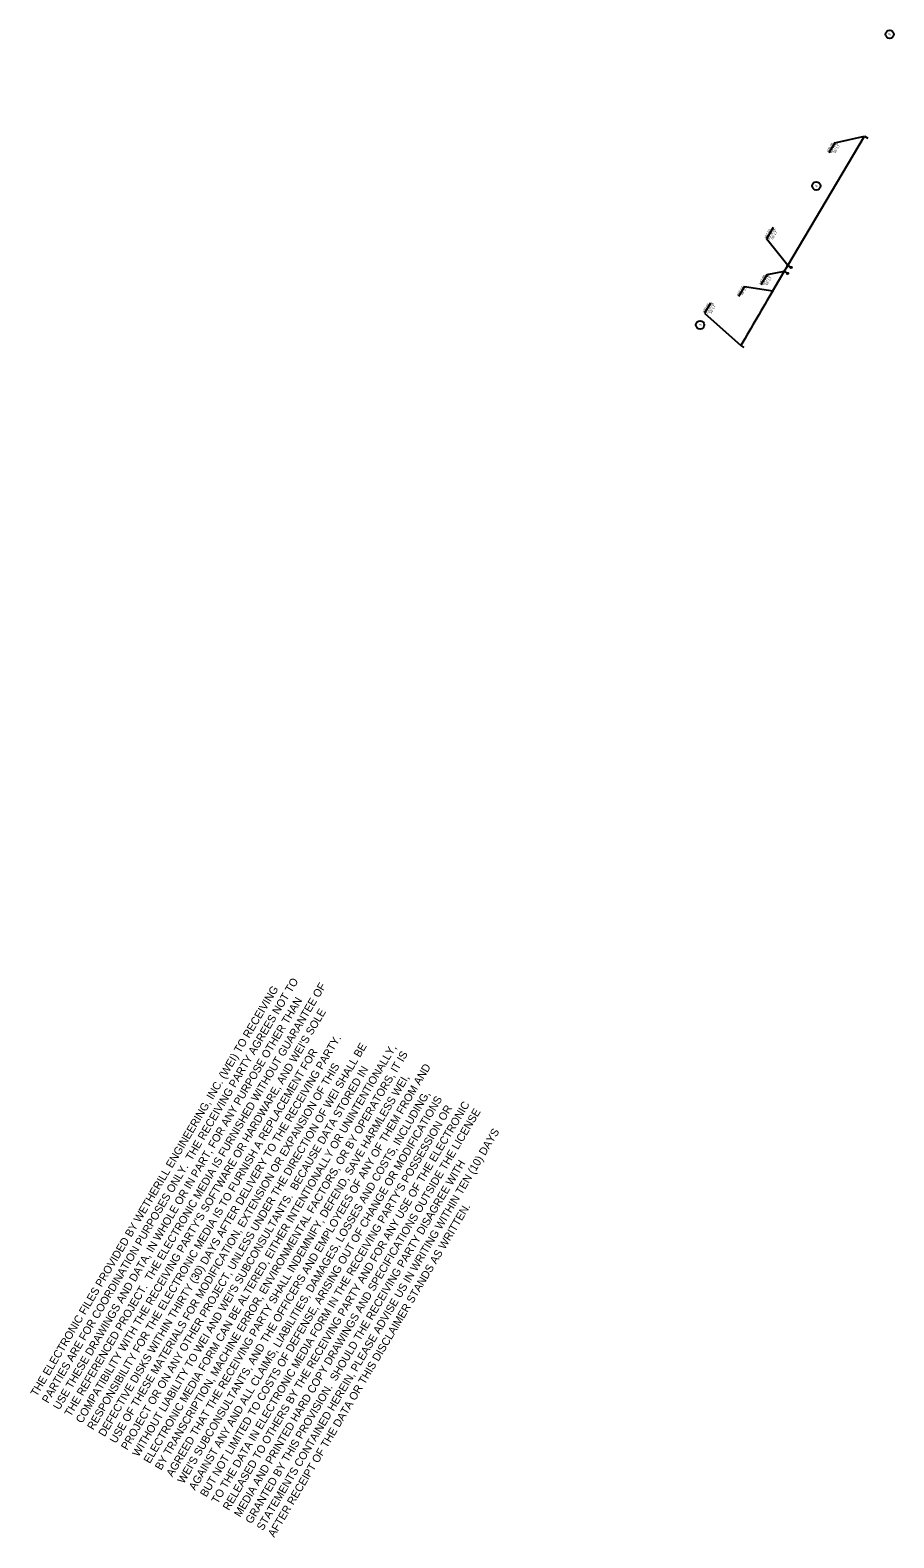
# Model space of a CAD drawing. Extents: x 2138768 to 2141259, y 406633 to 410979.
import ezdxf

# ---------------------------------------------------------------- set-up
doc = ezdxf.new("R2010")
doc.units = 0
for name, color, linetype in [('Default', 7, 'Continuous'), ('Prop Easement Construction', 7, 'Continuous'), ('Prop Easement Construction Station Offsets', 7, 'Continuous'), ('Prop Easement Permanent Drainage', 7, 'Continuous'), ('Prop Easement Permanent Drainage Station Offsets', 7, 'Continuous'), ('Prop Parcel Number CELL', 7, 'Continuous'), ('Prop ROW Marker CELL', 7, 'Continuous'), ('Prop ROW Permanent Easement CELL', 7, 'Continuous')]:
    doc.layers.add(name, color=color, linetype=linetype)

msp = doc.modelspace()

# ---------------------------------------------------------------- linework, layer by layer
at = {"layer": 'Prop Easement Construction'}
for p, q in [((2140952.9, 410300.7), (2141173.9, 410673)), ((2141173.9, 410673), (2141183.8, 410667.1)), ((2140909.6, 410227.8), (2140942.7, 410283.5)), ((2140817.4, 410069.5), (2140826.2, 410064.5))]:
    msp.add_line(p, q, dxfattribs=at)
msp.add_arc((2150502.2, 404534.3), 11155, 149.30926, 150.25022, dxfattribs=at)
at = {"layer": 'Prop Easement Construction Station Offsets'}
for p, q in [((2141088.6, 410654.4), (2141071.5, 410625.4)), ((2140828.3, 410240.4), (2140811.2, 410211.6)), ((2140730.4, 410191.8), (2140713.2, 410162.8))]:
    msp.add_line(p, q, dxfattribs=at)
for points in [[(2141088.6, 410654.4), (2141173.9, 410673)], [(2140828.3, 410240.4), (2140909.6, 410227.8)], [(2140713.2, 410162.8), (2140817.4, 410069.5)]]:
    msp.add_lwpolyline(points, dxfattribs=at)
at = {"layer": 'Prop Easement Permanent Drainage'}
for p, q in [((2140942.7, 410283.5), (2140952.9, 410300.7)), ((2140952.9, 410300.7), (2140962.8, 410294.8)), ((2140952.6, 410277.6), (2140942.7, 410283.5))]:
    msp.add_line(p, q, dxfattribs=at)
at = {"layer": 'Prop Easement Permanent Drainage Station Offsets'}
for p, q in [((2140910.5, 410409.8), (2140891.5, 410377.7)), ((2140952.9, 410300.7), (2140891.5, 410377.7)), ((2140892.4, 410273.6), (2140875.2, 410244.7)), ((2140942.7, 410283.5), (2140892.4, 410273.6))]:
    msp.add_line(p, q, dxfattribs=at)
at = {"layer": 'Prop Parcel Number CELL'}
for p, q in [((2141246.8, 410966.9), (2141246.8, 410966.9)), ((2141035.1, 410530), (2141035.1, 410530)), ((2140700, 410129.3), (2140700, 410129.3))]:
    msp.add_line(p, q, dxfattribs=at)
for centre in [(2141246.8, 410966.9), (2141035.1, 410530), (2140700, 410129.3)]:
    msp.add_circle(centre, 12, dxfattribs=at)
at = {"layer": 'Prop ROW Marker CELL'}
for p, q in [((2140952.9, 410300.7), (2140952.9, 410300.7)), ((2140962.8, 410294.8), (2140962.8, 410294.8)), ((2140942.7, 410283.5), (2140942.7, 410283.5)), ((2140952.6, 410277.6), (2140952.6, 410277.6))]:
    msp.add_line(p, q, dxfattribs=at)
at = {"layer": 'Prop ROW Permanent Easement CELL'}
for points in [[(2140951, 410301.8), (2140954, 410302.5), (2140954.7, 410299.6), (2140951.8, 410298.8)], [(2140952, 410301.2), (2140953.4, 410301.6), (2140953.8, 410300.1), (2140952.3, 410299.8)], [(2140961, 410295.9), (2140963.9, 410296.6), (2140964.7, 410293.7), (2140961.7, 410292.9)], [(2140961.9, 410295.3), (2140963.4, 410295.7), (2140963.8, 410294.2), (2140962.3, 410293.9)], [(2140940.8, 410284.6), (2140943.8, 410285.3), (2140944.5, 410282.4), (2140941.6, 410281.6)], [(2140941.7, 410284), (2140943.2, 410284.4), (2140943.6, 410282.9), (2140942.1, 410282.6)], [(2140950.8, 410278.7), (2140953.7, 410279.4), (2140954.5, 410276.5), (2140951.5, 410275.7)], [(2140951.7, 410278.1), (2140953.2, 410278.5), (2140953.6, 410277), (2140952.1, 410276.7)]]:
    msp.add_lwpolyline(points, close=True, dxfattribs=at)

# ---------------------------------------------------------------- texts
at = {"layer": 'Default'}
for s, p in [('THE ELECTRONIC FILES PROVIDED BY WETHERILL ENGINEERING, INC. (WEI) TO RECEIVING ', (2138787.2, 407038.8)), ('PARTIES ARE FOR COORDINATION PURPOSES ONLY.  THE RECEIVING PARTY AGREES NOT TO ', (2138819.8, 407019.4)), ('THE REFERENCED PROJECT.  THE ELECTRONIC MEDIA IS FURNISHED WITHOUT GUARANTEE OF ', (2138885, 406980.8)), ('USE THESE DRAWINGS AND DATA, IN WHOLE OR IN PART, FOR ANY PURPOSE OTHER THAN ', (2138852.4, 407000.1)), ("COMPATIBILITY WITH THE RECEIVING PARTY'S SOFTWARE OR HARDWARE, AND WEI'S SOLE ", (2138917.6, 406961.5)), ('DEFECTIVE DISKS WITHIN THIRTY (30) DAYS AFTER DELIVERY TO THE RECEIVING PARTY.  ', (2138982.8, 406922.8)), ('RESPONSIBILITY FOR THE ELECTRONIC MEDIA IS TO FURNISH A REPLACEMENT FOR ', (2138950.2, 406942.2)), ('PROJECT OR ON ANY OTHER PROJECT, UNLESS UNDER THE DIRECTION OF WEI SHALL BE ', (2139048, 406884.2)), ('ELECTRONIC MEDIA FORM CAN BE ALTERED, EITHER INTENTIONALLY OR UNINTENTIONALLY, ', (2139113.1, 406845.5)), ('BY TRANSCRIPTION, MACHINE ERROR, ENVIRONMENTAL FACTORS, OR BY OPERATORS, IT IS ', (2139145.7, 406826.2)), ('USE OF THESE MATERIALS FOR MODIFICATION, EXTENSION OR EXPANSION OF THIS ', (2139015.4, 406903.5)), ("WITHOUT LIABILITY TO WEI AND WEI'S SUBCONSULTANTS.  BECAUSE DATA STORED IN ", (2139080.6, 406864.9)), ("WEI'S SUBCONSULTANTS, AND THE OFFICERS AND EMPLOYEES OF ANY OF THEM FROM AND ", (2139210.9, 406787.6)), ('AGREED THAT THE RECEIVING PARTY SHALL INDEMNIFY, DEFEND, SAVE HARMLESS WEI, ', (2139178.3, 406806.9)), ('AGAINST ANY AND ALL CLAIMS, LIABILITIES, DAMAGES, LOSSES AND COSTS, INCLUDING, ', (2139243.5, 406768.3)), ('BUT NOT LIMITED TO COSTS OF DEFENSE, ARISING OUT OF CHANGE OR MODIFICATIONS ', (2139276.1, 406748.9)), ("TO THE DATA IN ELECTRONIC MEDIA FORM IN THE RECEIVING PARTY'S POSSESSION OR ", (2139308.7, 406729.6)), ('RELEASED TO OTHERS BY THE RECEIVING PARTY AND FOR ANY USE OF THE ELECTRONIC ', (2139341.3, 406710.3)), ('MEDIA AND PRINTED HARD COPY DRAWINGS AND SPECIFICATIONS OUTSIDE THE LICENSE ', (2139373.9, 406691)), ('STATEMENTS CONTAINED HEREIN, PLEASE ADVISE US IN WRITING WITHIN TEN (10) DAYS ', (2139439.1, 406652.3)), ('GRANTED BY THIS PROVISION.  SHOULD THE RECEIVING PARTY DISAGREE WITH ', (2139406.5, 406671.7)), ('AFTER RECEIPT OF THE DATA OR THIS DISCLAIMER STANDS AS WRITTEN.', (2139471.7, 406633))]:
    msp.add_text(s, height=22.733, rotation=59.3391, dxfattribs=at).set_placement(p)
at = {"layer": 'Prop Easement Construction Station Offsets'}
for s, p in [('+00.00', (2141070.1, 410625.8)), ('EX.R/W,', (2141079.4, 410623.9)), ("55' LT", (2141089.9, 410623.9)), ('+82.29', (2140810.1, 410211.7)), ("55' LT", (2140822.1, 410214.3)), ('+00.00', (2140712, 410163.1)), ('EX.R/W,', (2140721.3, 410161.2)), ("55' LT", (2140731.8, 410161.2))]:
    msp.add_text(s, height=7, rotation=59.3093, dxfattribs=at).set_placement(p)
at = {"layer": 'Prop Easement Permanent Drainage Station Offsets'}
for s, p in [('+67.00', (2140890.1, 410377)), ('EX.R/W,', (2140899.5, 410375.1)), ("55' LT", (2140909.9, 410375.1)), ('+47.00', (2140873.9, 410244.9)), ('EX.R/W,', (2140883.3, 410243.1)), ("55' LT", (2140893.8, 410243.1))]:
    msp.add_text(s, height=7, rotation=59.3093, dxfattribs=at).set_placement(p)
at = {"layer": 'Prop ROW Marker CELL'}
for s, p in [('2', (2141248.1, 410962.6)), ('2', (2141036.4, 410525.6)), ('1', (2140702.2, 410125.6))]:
    msp.add_text(s, height=7.5, rotation=59.3093, dxfattribs=at).set_placement(p)

doc.saveas('drawing.dxf')
